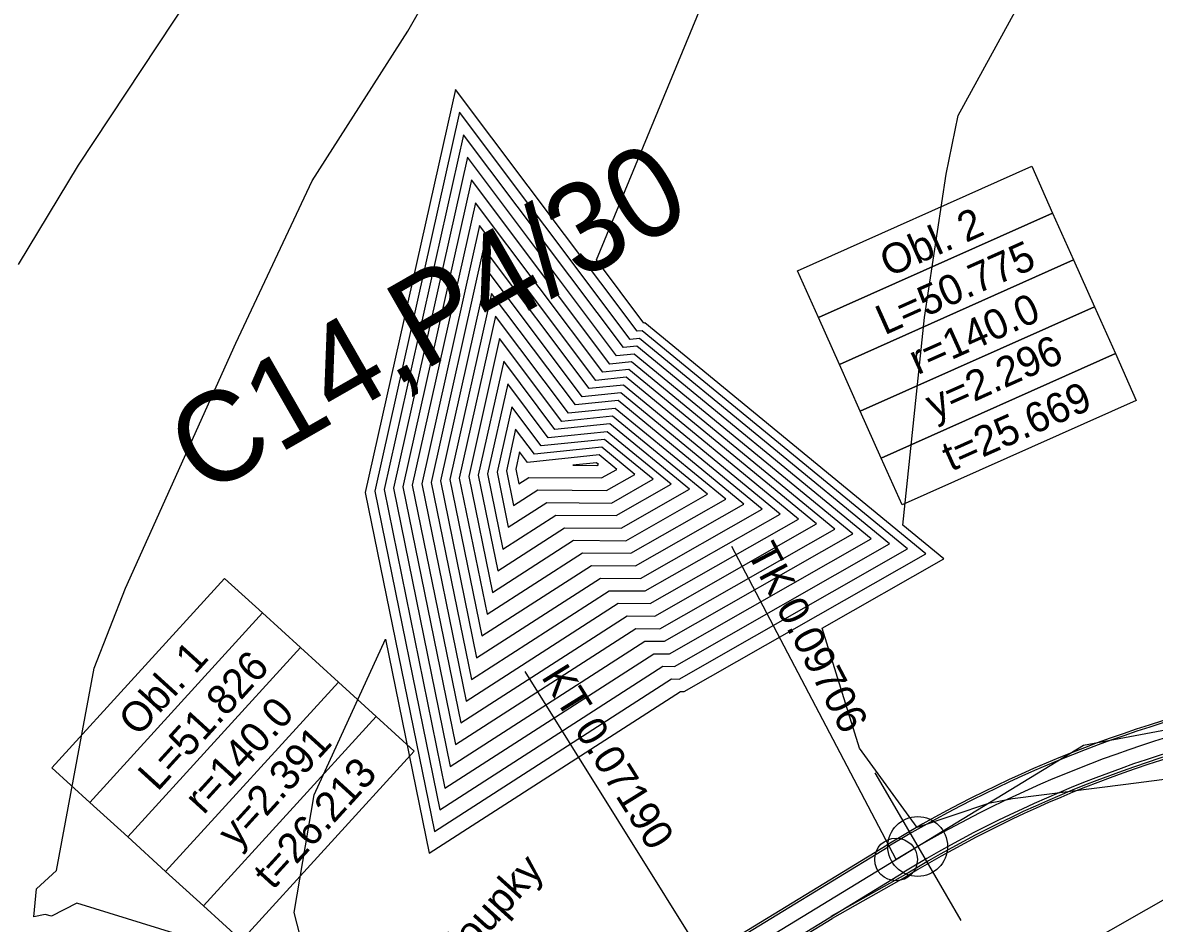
# Model space of a CAD drawing. Extents: x -549394 to -546608, y -1037055 to -1033629.
# Drawn here: x -547431.1 to -547298.7, y -1035202 to -1035096.6 of the extents above; entities that cross this region are included whole.
import ezdxf

# ---------------------------------------------------------------- set-up
doc = ezdxf.new("R2010")
doc.units = 0
for name, color, linetype in [('hlavni_vrst', 7, 'Continuous'), ('norm_vrst', 7, 'Continuous'), ('POLYGONY_SITUACE_PO', 7, 'Continuous'), ('u_sirka_1_5m', 7, 'Continuous'), ('x_navrh_C14', 7, 'Continuous'), ('x_osa_C14', 7, 'Continuous'), ('x_popis_oblouky_C14', 7, 'Continuous'), ('x_popis_pricne_rezy_C14', 7, 'Continuous'), ('x_popis_velky_C14', 7, 'Continuous'), ('x_SDZ_C141', 7, 'Continuous')]:
    doc.layers.add(name, color=color, linetype=linetype)

msp = doc.modelspace()

# ---------------------------------------------------------------- linework, layer by layer
at = {"layer": 'hlavni_vrst'}
for p, q in [((-547321.67, -1035107.49), (-547309.93, -1035086.01)), ((-547323.09, -1035114.37), (-547321.67, -1035107.49)), ((-547379.06, -1035112.39), (-547387.73, -1035151.11)), ((-547361.64, -1035135.62), (-547379.06, -1035112.39)), ((-547325.62, -1035131.12), (-547323.09, -1035114.37)), ((-547376.72, -1035125.65), (-547382.23, -1035150.26)), ((-547365.64, -1035140.41), (-547376.72, -1035125.65)), ((-547328.15, -1035155.42), (-547325.62, -1035131.12)), ((-547359.58, -1035135.41), (-547361.64, -1035135.62)), ((-547333.98, -1035156.47), (-547359.58, -1035135.41)), ((-547374.37, -1035138.91), (-547376.72, -1035149.41)), ((-547369.65, -1035145.21), (-547374.37, -1035138.91)), ((-547361.15, -1035139.95), (-547365.64, -1035140.41)), ((-547344.61, -1035153.56), (-547361.15, -1035139.95)), ((-547362.72, -1035144.5), (-547369.65, -1035145.21)), ((-547355.24, -1035150.65), (-547362.72, -1035144.5)), ((-547376.72, -1035149.41), (-547374.92, -1035158.24)), ((-547387.73, -1035151.11), (-547381.09, -1035183.66)), ((-547382.23, -1035150.26), (-547378.01, -1035170.95)), ((-547361.68, -1035154.32), (-547355.24, -1035150.65)), ((-547358.84, -1035161.67), (-547344.61, -1035153.56)), ((-547374.92, -1035158.24), (-547368.75, -1035154.26)), ((-547368.75, -1035154.26), (-547361.68, -1035154.32)), ((-547356.01, -1035169.02), (-547333.98, -1035156.47)), ((-547323.35, -1035159.37), (-547328.15, -1035155.42)), ((-547337.6, -1035167.5), (-547323.35, -1035159.37)), ((-547378.01, -1035170.95), (-547363.53, -1035161.63)), ((-547363.53, -1035161.63), (-547358.84, -1035161.67)), ((-547333.21, -1035181.55), (-547337.6, -1035167.5)), ((-547381.09, -1035183.66), (-547358.32, -1035169.01)), ((-547358.32, -1035169.01), (-547356.01, -1035169.02)), ((-547326.47, -1035190.83), (-547333.21, -1035181.55)), ((-547289.76, -1035184.18), (-547302.05, -1035185.79)), ((-547302.05, -1035185.79), (-547315.3, -1035187.46)), ((-547318.11, -1035188.02), (-547326.47, -1035190.83)), ((-547315.3, -1035187.46), (-547318.11, -1035188.02)), ((-547317.64, -1035210.67), (-547292.9, -1035196.54))]:
    msp.add_line(p, q, dxfattribs=at)
at = {"layer": 'norm_vrst'}
for p, q in [((-547386.05, -1035097.61), (-547379.26, -1035085.64)), ((-547424.58, -1035113.3), (-547408.42, -1035088.9)), ((-547363.97, -1035124.4), (-547351.76, -1035094.86)), ((-547397.23, -1035115.14), (-547386.05, -1035097.61)), ((-547380.47, -1035104.44), (-547391.03, -1035151.62)), ((-547359.24, -1035132.74), (-547380.47, -1035104.44)), ((-547380, -1035107.09), (-547389.93, -1035151.45)), ((-547360.04, -1035133.7), (-547380, -1035107.09)), ((-547379.53, -1035109.74), (-547388.83, -1035151.28)), ((-547360.84, -1035134.66), (-547379.53, -1035109.74)), ((-547431.58, -1035124.92), (-547424.58, -1035113.3)), ((-547406.17, -1035134.15), (-547397.23, -1035115.14)), ((-547378.59, -1035115.04), (-547386.63, -1035150.94)), ((-547362.44, -1035136.58), (-547378.59, -1035115.04)), ((-547378.12, -1035117.7), (-547385.53, -1035150.77)), ((-547363.24, -1035137.54), (-547378.12, -1035117.7)), ((-547377.65, -1035120.35), (-547384.43, -1035150.6)), ((-547364.04, -1035138.5), (-547377.65, -1035120.35)), ((-547377.19, -1035123), (-547383.33, -1035150.43)), ((-547364.84, -1035139.46), (-547377.19, -1035123)), ((-547358.43, -1035131.78), (-547363.97, -1035124.4)), ((-547376.25, -1035128.31), (-547381.13, -1035150.09)), ((-547366.45, -1035141.37), (-547376.25, -1035128.31)), ((-547375.78, -1035130.96), (-547380.03, -1035149.92)), ((-547367.25, -1035142.33), (-547375.78, -1035130.96)), ((-547358.64, -1035132.68), (-547359.24, -1035132.74)), ((-547327.6, -1035158.21), (-547358.64, -1035132.68)), ((-547358.32, -1035131.77), (-547358.43, -1035131.78)), ((-547325.47, -1035158.79), (-547358.32, -1035131.77)), ((-547375.31, -1035133.61), (-547378.93, -1035149.75)), ((-547368.05, -1035143.29), (-547375.31, -1035133.61)), ((-547358.95, -1035133.59), (-547360.04, -1035133.7)), ((-547329.72, -1035157.63), (-547358.95, -1035133.59)), ((-547419.09, -1035162.8), (-547406.17, -1035134.15)), ((-547359.27, -1035134.5), (-547360.84, -1035134.66)), ((-547331.85, -1035157.05), (-547359.27, -1035134.5)), ((-547374.84, -1035136.26), (-547377.82, -1035149.58)), ((-547368.85, -1035144.25), (-547374.84, -1035136.26)), ((-547359.89, -1035136.31), (-547362.44, -1035136.58)), ((-547336.1, -1035155.89), (-547359.89, -1035136.31)), ((-547360.21, -1035137.22), (-547363.24, -1035137.54)), ((-547338.23, -1035155.3), (-547360.21, -1035137.22)), ((-547360.84, -1035139.04), (-547364.84, -1035139.46)), ((-547360.52, -1035138.13), (-547364.04, -1035138.5)), ((-547342.48, -1035154.14), (-547360.84, -1035139.04)), ((-547340.36, -1035154.72), (-547360.52, -1035138.13)), ((-547373.9, -1035141.57), (-547375.62, -1035149.24)), ((-547370.45, -1035146.17), (-547373.9, -1035141.57)), ((-547361.78, -1035141.77), (-547367.25, -1035142.33)), ((-547361.46, -1035140.86), (-547366.45, -1035141.37)), ((-547348.86, -1035152.4), (-547361.78, -1035141.77)), ((-547346.73, -1035152.98), (-547361.46, -1035140.86)), ((-547362.09, -1035142.68), (-547368.05, -1035143.29)), ((-547350.99, -1035151.81), (-547362.09, -1035142.68)), ((-547373.44, -1035144.22), (-547374.52, -1035149.07)), ((-547371.25, -1035147.13), (-547373.44, -1035144.22)), ((-547362.41, -1035143.59), (-547368.85, -1035144.25)), ((-547353.11, -1035151.23), (-547362.41, -1035143.59)), ((-547363.04, -1035145.4), (-547370.45, -1035146.17)), ((-547357.37, -1035150.07), (-547363.04, -1035145.4)), ((-547372.97, -1035146.87), (-547373.42, -1035148.9)), ((-547372.05, -1035148.09), (-547372.97, -1035146.87)), ((-547363.66, -1035147.22), (-547372.05, -1035148.09)), ((-547363.35, -1035146.31), (-547371.25, -1035147.13)), ((-547361.62, -1035148.91), (-547363.66, -1035147.22)), ((-547359.49, -1035149.49), (-547363.35, -1035146.31)), ((-547363.98, -1035148.13), (-547366.75, -1035148.42)), ((-547366.75, -1035148.42), (-547363.95, -1035148.44)), ((-547363.74, -1035148.33), (-547363.98, -1035148.13)), ((-547363.95, -1035148.44), (-547363.74, -1035148.33)), ((-547380.03, -1035149.92), (-547376.77, -1035165.86)), ((-547378.93, -1035149.75), (-547376.16, -1035163.32)), ((-547377.82, -1035149.58), (-547375.54, -1035160.78)), ((-547375.62, -1035149.24), (-547374.31, -1035155.69)), ((-547374.52, -1035149.07), (-547373.69, -1035153.15)), ((-547373.42, -1035148.9), (-547373.07, -1035150.61)), ((-547373.07, -1035150.61), (-547371.88, -1035149.84)), ((-547371.88, -1035149.84), (-547363.38, -1035149.91)), ((-547363.38, -1035149.91), (-547361.62, -1035148.91)), ((-547362.81, -1035151.38), (-547359.49, -1035149.49)), ((-547388.83, -1035151.28), (-547381.71, -1035186.2)), ((-547386.63, -1035150.94), (-547380.47, -1035181.11)), ((-547385.53, -1035150.77), (-547379.86, -1035178.57)), ((-547384.43, -1035150.6), (-547379.24, -1035176.03)), ((-547383.33, -1035150.43), (-547378.62, -1035173.49)), ((-547381.13, -1035150.09), (-547377.39, -1035168.4)), ((-547362.24, -1035152.85), (-547357.37, -1035150.07)), ((-547361.11, -1035155.79), (-547353.11, -1035151.23)), ((-547391.03, -1035151.62), (-547382.94, -1035191.28)), ((-547389.93, -1035151.45), (-547382.32, -1035188.74)), ((-547373.69, -1035153.15), (-547370.84, -1035151.32)), ((-547370.84, -1035151.32), (-547362.81, -1035151.38)), ((-547360.54, -1035157.26), (-547350.99, -1035151.81)), ((-547359.98, -1035158.73), (-547348.86, -1035152.4)), ((-547374.31, -1035155.69), (-547369.79, -1035152.79)), ((-547369.79, -1035152.79), (-547362.24, -1035152.85)), ((-547359.41, -1035160.2), (-547346.73, -1035152.98)), ((-547358.27, -1035163.14), (-547342.48, -1035154.14)), ((-547357.71, -1035164.61), (-547340.36, -1035154.72)), ((-547375.54, -1035160.78), (-547367.71, -1035155.74)), ((-547367.71, -1035155.74), (-547361.11, -1035155.79)), ((-547357.14, -1035166.08), (-547338.23, -1035155.3)), ((-547356.57, -1035167.55), (-547336.1, -1035155.89)), ((-547376.16, -1035163.32), (-547366.66, -1035157.21)), ((-547366.66, -1035157.21), (-547360.54, -1035157.26)), ((-547355.44, -1035170.49), (-547331.85, -1035157.05)), ((-547354.87, -1035171.97), (-547329.72, -1035157.63)), ((-547376.77, -1035165.86), (-547365.62, -1035158.69)), ((-547365.62, -1035158.69), (-547359.98, -1035158.73)), ((-547354.3, -1035173.44), (-547327.6, -1035158.21)), ((-547353.74, -1035174.91), (-547325.47, -1035158.79)), ((-547377.39, -1035168.4), (-547364.58, -1035160.16)), ((-547364.58, -1035160.16), (-547359.41, -1035160.2)), ((-547422.74, -1035172.18), (-547419.09, -1035162.8)), ((-547378.62, -1035173.49), (-547362.49, -1035163.11)), ((-547362.49, -1035163.11), (-547358.27, -1035163.14)), ((-547379.24, -1035176.03), (-547361.45, -1035164.58)), ((-547361.45, -1035164.58), (-547357.71, -1035164.61)), ((-547379.86, -1035178.57), (-547360.41, -1035166.06)), ((-547360.41, -1035166.06), (-547357.14, -1035166.08)), ((-547380.47, -1035181.11), (-547359.36, -1035167.53)), ((-547359.36, -1035167.53), (-547356.57, -1035167.55)), ((-547397.01, -1035186.98), (-547388.67, -1035168.78)), ((-547388.67, -1035168.78), (-547383.56, -1035193.82)), ((-547381.71, -1035186.2), (-547357.28, -1035170.48)), ((-547357.28, -1035170.48), (-547355.44, -1035170.49)), ((-547427.14, -1035195.86), (-547422.74, -1035172.18)), ((-547382.32, -1035188.74), (-547356.23, -1035171.95)), ((-547356.23, -1035171.95), (-547354.87, -1035171.97)), ((-547382.94, -1035191.28), (-547355.19, -1035173.43)), ((-547355.19, -1035173.43), (-547354.3, -1035173.44)), ((-547383.56, -1035193.82), (-547354.15, -1035174.9)), ((-547354.15, -1035174.9), (-547353.74, -1035174.91)), ((-547399.36, -1035200.76), (-547397.01, -1035186.98)), ((-547429.5, -1035198), (-547427.14, -1035195.86)), ((-547429.8, -1035201.29), (-547429.5, -1035198)), ((-547424.77, -1035199.66), (-547427.75, -1035201.2)), ((-547406.29, -1035205.37), (-547424.77, -1035199.66)), ((-547428.49, -1035201), (-547429.8, -1035201.29)), ((-547427.75, -1035201.2), (-547428.49, -1035201)), ((-547396.7, -1035211.13), (-547399.36, -1035200.76))]:
    msp.add_line(p, q, dxfattribs=at)
at = {"layer": 'POLYGONY_SITUACE_PO'}
msp.add_circle((-547328.94, -1035194.55), 2.5, dxfattribs=at)
at = {"layer": 'u_sirka_1_5m'}
msp.add_circle((-547326.41, -1035193.04), 3.5, dxfattribs=at)
at = {"layer": 'x_navrh_C14'}
for p, q in [((-547351.45, -1035205.95), (-547329.98, -1035192.84)), ((-547351.32, -1035206.16), (-547329.85, -1035193.06)), ((-547349.5, -1035209.15), (-547328.02, -1035196.04)), ((-547327.85, -1035196.33), (-547336.56, -1035201.25)), ((-547327.72, -1035196.55), (-547336.43, -1035201.47)), ((-547340.83, -1035204.15), (-547336.43, -1035201.47))]:
    msp.add_line(p, q, dxfattribs=at)
for radius, start, end in [(142, 100.6108, 121.3907), (141.75, 100.6108, 121.3907), (138.25, 100.6108, 121.3907), (137.91, 100.6108, 121.3907), (137.66, 100.609, 121.3924)]:
    msp.add_arc((-547256.01, -1035314.06), radius, start, end, dxfattribs=at)
at = {"layer": 'x_osa_C14'}
for points in [[(-547307.02, -1035181.18), (-547270.54, -1035174.35), (-547253.23, -1035162.86)], [(-547372.79, -1035221.31), (-547307.02, -1035181.18)]]:
    msp.add_lwpolyline(points, dxfattribs=at)
msp.add_arc((-547256.01, -1035314.06), 140, 100.6108, 121.3907, dxfattribs=at)
at = {"layer": 'x_popis_oblouky_C14'}
for points in [[(-547340.46, -1035125.67), (-547313.06, -1035113.44), (-547310.62, -1035118.92), (-547338.01, -1035131.15)], [(-547338.01, -1035131.15), (-547310.62, -1035118.92), (-547308.17, -1035124.4), (-547335.57, -1035136.63)], [(-547335.57, -1035136.63), (-547308.17, -1035124.4), (-547305.73, -1035129.88), (-547333.12, -1035142.11)], [(-547333.12, -1035142.11), (-547305.73, -1035129.88), (-547303.28, -1035135.36), (-547330.68, -1035147.59)], [(-547330.68, -1035147.59), (-547303.28, -1035135.36), (-547300.84, -1035140.84), (-547328.23, -1035153.07)], [(-547427.69, -1035183.84), (-547407.48, -1035161.66), (-547403.04, -1035165.71), (-547423.25, -1035187.88)], [(-547423.25, -1035187.88), (-547403.04, -1035165.71), (-547398.61, -1035169.75), (-547418.82, -1035191.92)], [(-547418.82, -1035191.92), (-547398.61, -1035169.75), (-547394.17, -1035173.79), (-547414.38, -1035195.96)], [(-547414.38, -1035195.96), (-547394.17, -1035173.79), (-547389.74, -1035177.83), (-547409.95, -1035200)], [(-547409.95, -1035200), (-547389.74, -1035177.83), (-547385.31, -1035181.87), (-547405.51, -1035204.05)]]:
    msp.add_lwpolyline(points, close=True, dxfattribs=at)
for points in [[(-547328.94, -1035194.55), (-547348.16, -1035157.92)], [(-547350.41, -1035207.65), (-547372.32, -1035172.56)]]:
    msp.add_lwpolyline(points, dxfattribs=at)
at = {"layer": 'x_popis_pricne_rezy_C14'}
msp.add_lwpolyline([(-547331.44, -1035184.4), (-547326.41, -1035193.04), (-547321.38, -1035201.69)], dxfattribs=at)

# ---------------------------------------------------------------- texts
at = {"layer": 'x_popis_oblouky_C14'}
for s, rotation, p in [('Obl. 2', 24.0792, (-547329.8, -1035126.45)), ('L=50.775', 24.0792, (-547330.29, -1035133.24)), ('r=140.0', 24.0792, (-547326.42, -1035137.89)), ('y=2.296', 24.0792, (-547324.47, -1035143.11)), ('t=25.669', 24.0792, (-547322.52, -1035149.2)), ('TK 0.09706', 297.6923, (-547346.42, -1035158.64)), ('Obl. 1', 47.6745, (-547417.61, -1035180.29)), ('L=51.826', 47.6745, (-547415.33, -1035186.7)), ('KT 0.07190', 301.9821, (-547370.51, -1035173.19)), ('r=140.0', 47.6745, (-547409.93, -1035189.42)), ('y=2.391', 47.6745, (-547406.06, -1035193.42)), ('t=26.213', 47.6745, (-547401.83, -1035198.22))]:
    msp.add_text(s, height=3.5, rotation=rotation, dxfattribs=at).set_placement(p)
at = {"layer": 'x_popis_velky_C14'}
msp.add_text('C14,P4/30', height=10.5, rotation=29.8461, dxfattribs=at).set_placement((-547409.98, -1035152.2))
at = {"layer": 'x_SDZ_C141'}
msp.add_text('Směrové sloupky', height=3.5, rotation=47.8559, dxfattribs=at).set_placement((-547394.1, -1035222.55))

doc.saveas('drawing.dxf')
